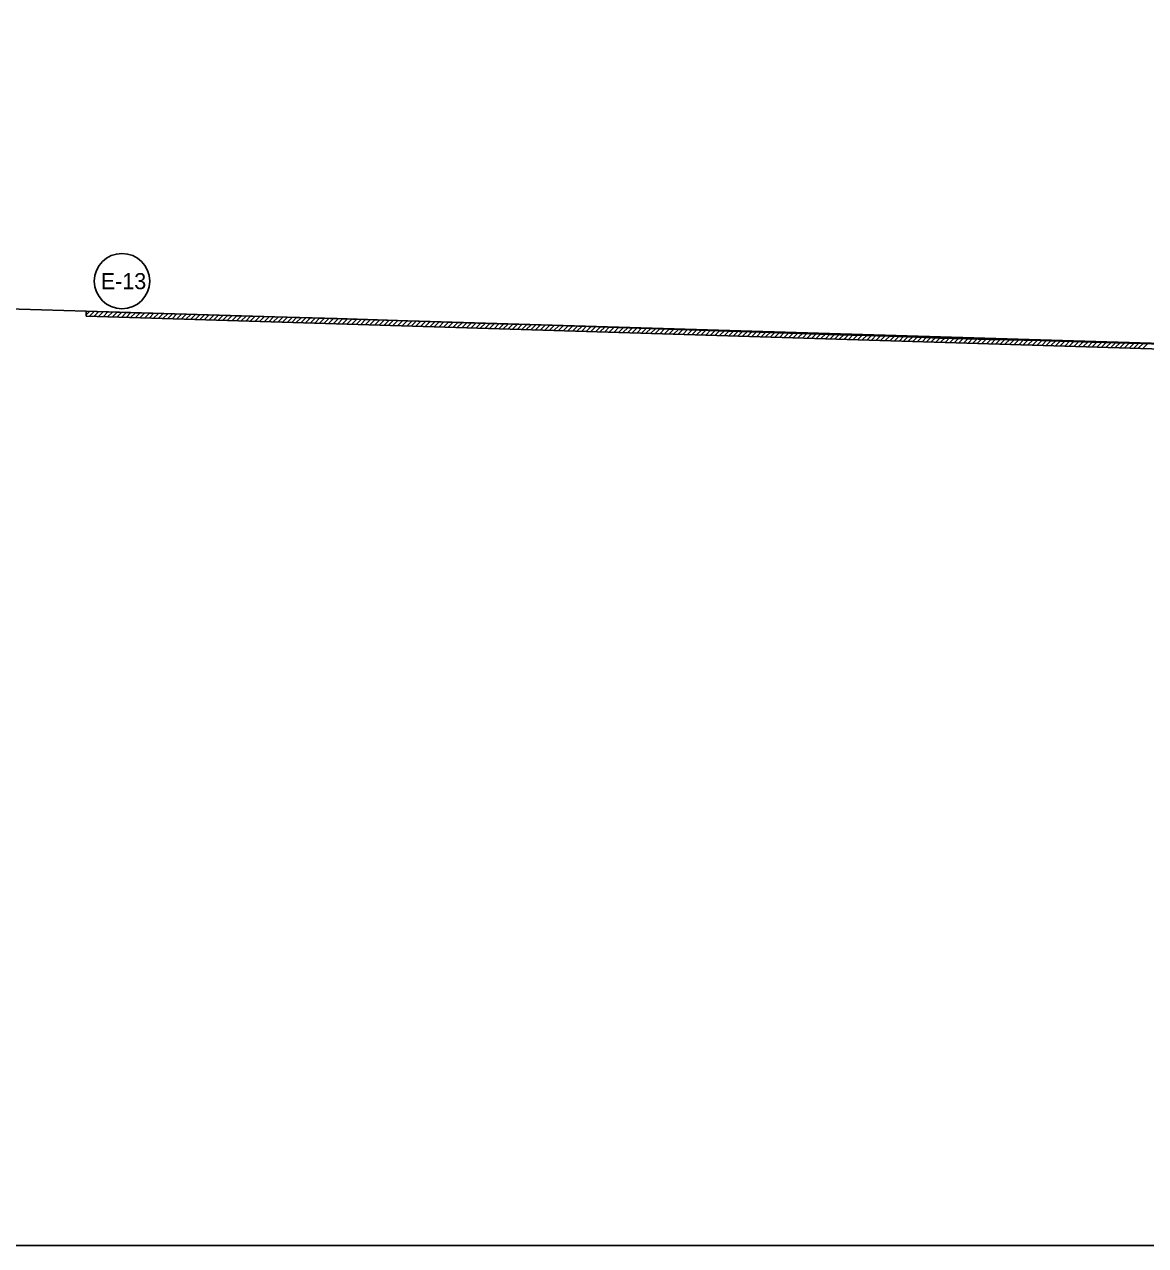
# Model space of a CAD drawing. Extents: x 976877 to 983987, y 1525984 to 1526526.
# Drawn here: x 982962.3 to 983296.7, y 1526043.8 to 1526408 of the extents above; entities that cross this region are included whole.
import ezdxf

# ---------------------------------------------------------------- set-up
doc = ezdxf.new("R2010")
doc.units = 0
doc.layers.add('R_Erosion', color=7, linetype='Continuous')
doc.layers.add('R_No Plot', color=7, linetype='Continuous')

msp = doc.modelspace()

# ---------------------------------------------------------------- linework, layer by layer
at = {"layer": 'R_Erosion'}
for p, q in [((982980.66, 1526320.94), (982980.7, 1526322.43)), ((982980.67, 1526321.39), (982981.69, 1526322.4)), ((982980.7, 1526322.43), (983619.57, 1526303.24)), ((982981.6, 1526320.91), (982983.06, 1526322.36)), ((982982.98, 1526320.86), (982984.43, 1526322.32)), ((982984.35, 1526320.82), (982985.81, 1526322.28)), ((982985.72, 1526320.78), (982987.18, 1526322.24)), ((982987.09, 1526320.74), (982988.55, 1526322.2)), ((982988.47, 1526320.7), (982989.93, 1526322.16)), ((982989.84, 1526320.66), (982991.3, 1526322.12)), ((982991.21, 1526320.61), (982992.67, 1526322.07)), ((982992.58, 1526320.57), (982994.04, 1526322.03)), ((982993.95, 1526320.53), (982995.42, 1526321.99)), ((982995.33, 1526320.49), (982996.79, 1526321.95)), ((982996.7, 1526320.45), (982998.16, 1526321.91)), ((982998.07, 1526320.4), (982999.54, 1526321.87)), ((983619.52, 1526301.48), (982980.66, 1526320.94)), ((982999.44, 1526320.36), (983000.91, 1526321.83)), ((983000.82, 1526320.32), (983002.28, 1526321.79)), ((983002.19, 1526320.28), (983003.65, 1526321.74)), ((983003.56, 1526320.24), (983005.03, 1526321.7)), ((983004.93, 1526320.2), (983006.4, 1526321.66)), ((983006.31, 1526320.15), (983007.77, 1526321.62)), ((983007.68, 1526320.11), (983009.15, 1526321.58)), ((983009.05, 1526320.07), (983010.52, 1526321.54)), ((983010.42, 1526320.03), (983011.89, 1526321.5)), ((983011.8, 1526319.99), (983013.27, 1526321.46)), ((983013.17, 1526319.94), (983014.64, 1526321.41)), ((983014.54, 1526319.9), (983016.01, 1526321.37)), ((983015.91, 1526319.86), (983017.38, 1526321.33)), ((983017.29, 1526319.82), (983018.76, 1526321.29)), ((983018.66, 1526319.78), (983020.13, 1526321.25)), ((983020.03, 1526319.74), (983021.5, 1526321.21)), ((983021.4, 1526319.69), (983022.88, 1526321.17)), ((983022.78, 1526319.65), (983024.25, 1526321.13)), ((983024.15, 1526319.61), (983025.62, 1526321.08)), ((983025.52, 1526319.57), (983027, 1526321.04)), ((983026.89, 1526319.53), (983028.37, 1526321)), ((983028.27, 1526319.49), (983029.74, 1526320.96)), ((983029.64, 1526319.44), (983031.11, 1526320.92)), ((983031.01, 1526319.4), (983032.49, 1526320.88)), ((983032.38, 1526319.36), (983033.86, 1526320.84)), ((983033.75, 1526319.32), (983035.23, 1526320.8)), ((983035.13, 1526319.28), (983036.61, 1526320.75)), ((983036.5, 1526319.23), (983037.98, 1526320.71)), ((983037.87, 1526319.19), (983039.35, 1526320.67)), ((983039.24, 1526319.15), (983040.72, 1526320.63)), ((983040.62, 1526319.11), (983042.1, 1526320.59)), ((983041.99, 1526319.07), (983043.47, 1526320.55)), ((983043.36, 1526319.03), (983044.84, 1526320.51)), ((983044.73, 1526318.98), (983046.22, 1526320.47)), ((983046.11, 1526318.94), (983047.59, 1526320.42)), ((983047.48, 1526318.9), (983048.96, 1526320.38)), ((983048.85, 1526318.86), (983050.34, 1526320.34)), ((983050.22, 1526318.82), (983051.71, 1526320.3)), ((983051.6, 1526318.77), (983053.08, 1526320.26)), ((983052.97, 1526318.73), (983054.45, 1526320.22)), ((983054.34, 1526318.69), (983055.83, 1526320.18)), ((983055.71, 1526318.65), (983057.2, 1526320.14)), ((983057.09, 1526318.61), (983058.57, 1526320.09)), ((983058.46, 1526318.57), (983059.95, 1526320.05)), ((983059.83, 1526318.52), (983061.32, 1526320.01)), ((983061.2, 1526318.48), (983062.69, 1526319.97)), ((983062.58, 1526318.44), (983064.06, 1526319.93)), ((983063.95, 1526318.4), (983065.44, 1526319.89)), ((983065.32, 1526318.36), (983066.81, 1526319.85)), ((983066.69, 1526318.31), (983068.18, 1526319.81)), ((983068.07, 1526318.27), (983069.56, 1526319.76)), ((983069.44, 1526318.23), (983070.93, 1526319.72)), ((983070.81, 1526318.19), (983072.3, 1526319.68)), ((983072.18, 1526318.15), (983073.68, 1526319.64)), ((983073.56, 1526318.11), (983075.05, 1526319.6)), ((983074.93, 1526318.06), (983076.42, 1526319.56)), ((983076.3, 1526318.02), (983077.79, 1526319.52)), ((983077.67, 1526317.98), (983079.17, 1526319.48)), ((983079.04, 1526317.94), (983080.54, 1526319.43)), ((983080.42, 1526317.9), (983081.91, 1526319.39)), ((983081.79, 1526317.85), (983083.29, 1526319.35)), ((983083.16, 1526317.81), (983084.66, 1526319.31)), ((983084.53, 1526317.77), (983086.03, 1526319.27)), ((983085.91, 1526317.73), (983087.41, 1526319.23)), ((983087.28, 1526317.69), (983088.78, 1526319.19)), ((983088.65, 1526317.65), (983090.15, 1526319.15)), ((983090.02, 1526317.6), (983091.52, 1526319.1)), ((983091.4, 1526317.56), (983092.9, 1526319.06)), ((983092.77, 1526317.52), (983094.27, 1526319.02)), ((983094.14, 1526317.48), (983095.64, 1526318.98)), ((983095.51, 1526317.44), (983097.02, 1526318.94)), ((983096.89, 1526317.4), (983098.39, 1526318.9)), ((983098.26, 1526317.35), (983099.76, 1526318.86)), ((983099.63, 1526317.31), (983101.13, 1526318.82)), ((983101, 1526317.27), (983102.51, 1526318.77)), ((983102.38, 1526317.23), (983103.88, 1526318.73)), ((983103.75, 1526317.19), (983105.25, 1526318.69)), ((983105.12, 1526317.14), (983106.63, 1526318.65)), ((983106.49, 1526317.1), (983108, 1526318.61)), ((983107.87, 1526317.06), (983109.37, 1526318.57)), ((983109.24, 1526317.02), (983110.75, 1526318.53)), ((983110.61, 1526316.98), (983112.12, 1526318.49)), ((983111.98, 1526316.94), (983113.49, 1526318.44)), ((983113.36, 1526316.89), (983114.86, 1526318.4)), ((983114.73, 1526316.85), (983116.24, 1526318.36)), ((983116.1, 1526316.81), (983117.61, 1526318.32)), ((983117.47, 1526316.77), (983118.98, 1526318.28)), ((983118.84, 1526316.73), (983120.36, 1526318.24)), ((983120.22, 1526316.68), (983121.73, 1526318.2)), ((983121.59, 1526316.64), (983123.1, 1526318.16)), ((983122.96, 1526316.6), (983124.48, 1526318.11)), ((983124.33, 1526316.56), (983125.85, 1526318.07)), ((983125.71, 1526316.52), (983127.22, 1526318.03)), ((983127.08, 1526316.48), (983128.59, 1526317.99)), ((983128.45, 1526316.43), (983129.97, 1526317.95)), ((983129.82, 1526316.39), (983131.34, 1526317.91)), ((983131.2, 1526316.35), (983132.71, 1526317.87)), ((983132.57, 1526316.31), (983134.09, 1526317.83)), ((983133.94, 1526316.27), (983135.46, 1526317.78)), ((983135.31, 1526316.23), (983136.83, 1526317.74)), ((983136.69, 1526316.18), (983138.2, 1526317.7)), ((983138.06, 1526316.14), (983139.58, 1526317.66)), ((983139.43, 1526316.1), (983140.95, 1526317.62)), ((983140.8, 1526316.06), (983142.32, 1526317.58)), ((983142.18, 1526316.02), (983143.7, 1526317.54)), ((983143.55, 1526315.97), (983145.07, 1526317.5)), ((983144.92, 1526315.93), (983146.44, 1526317.45)), ((983146.29, 1526315.89), (983147.82, 1526317.41)), ((983147.67, 1526315.85), (983149.19, 1526317.37)), ((983149.04, 1526315.81), (983150.56, 1526317.33)), ((983150.41, 1526315.77), (983151.93, 1526317.29)), ((983151.78, 1526315.72), (983153.31, 1526317.25)), ((983153.16, 1526315.68), (983154.68, 1526317.21)), ((983154.53, 1526315.64), (983156.05, 1526317.17)), ((983155.9, 1526315.6), (983157.43, 1526317.12)), ((983157.27, 1526315.56), (983158.8, 1526317.08)), ((983158.64, 1526315.51), (983160.17, 1526317.04)), ((983160.02, 1526315.47), (983161.55, 1526317)), ((983161.39, 1526315.43), (983162.92, 1526316.96)), ((983162.76, 1526315.39), (983164.29, 1526316.92)), ((983164.13, 1526315.35), (983165.66, 1526316.88)), ((983165.51, 1526315.31), (983167.04, 1526316.84)), ((983166.88, 1526315.26), (983168.41, 1526316.79)), ((983168.25, 1526315.22), (983169.78, 1526316.75)), ((983169.62, 1526315.18), (983171.16, 1526316.71)), ((983171, 1526315.14), (983172.53, 1526316.67)), ((983172.37, 1526315.1), (983173.9, 1526316.63)), ((983173.74, 1526315.05), (983175.27, 1526316.59)), ((983175.11, 1526315.01), (983176.65, 1526316.55)), ((983176.49, 1526314.97), (983178.02, 1526316.51)), ((983177.86, 1526314.93), (983179.39, 1526316.46)), ((983179.23, 1526314.89), (983180.77, 1526316.42)), ((983180.6, 1526314.85), (983182.14, 1526316.38)), ((983181.98, 1526314.8), (983183.51, 1526316.34)), ((983183.35, 1526314.76), (983184.89, 1526316.3)), ((983184.72, 1526314.72), (983186.26, 1526316.26)), ((983186.09, 1526314.68), (983187.63, 1526316.22)), ((983187.47, 1526314.64), (983189, 1526316.18)), ((983188.84, 1526314.59), (983190.38, 1526316.13)), ((983190.21, 1526314.55), (983191.75, 1526316.09)), ((983191.58, 1526314.51), (983193.12, 1526316.05)), ((983192.96, 1526314.47), (983194.5, 1526316.01)), ((983194.33, 1526314.43), (983195.87, 1526315.97)), ((983195.7, 1526314.39), (983197.24, 1526315.93)), ((983197.07, 1526314.34), (983198.61, 1526315.89)), ((983198.44, 1526314.3), (983199.99, 1526315.85)), ((983199.82, 1526314.26), (983201.36, 1526315.8)), ((983201.19, 1526314.22), (983202.73, 1526315.76)), ((983202.56, 1526314.18), (983204.11, 1526315.72)), ((983203.93, 1526314.14), (983205.48, 1526315.68)), ((983205.31, 1526314.09), (983206.85, 1526315.64)), ((983206.68, 1526314.05), (983208.23, 1526315.6)), ((983208.05, 1526314.01), (983209.6, 1526315.56)), ((983209.42, 1526313.97), (983210.97, 1526315.52)), ((983210.8, 1526313.93), (983212.34, 1526315.47)), ((983212.17, 1526313.88), (983213.72, 1526315.43)), ((983213.54, 1526313.84), (983215.09, 1526315.39)), ((983214.91, 1526313.8), (983216.46, 1526315.35)), ((983216.29, 1526313.76), (983217.84, 1526315.31)), ((983217.66, 1526313.72), (983219.21, 1526315.27)), ((983219.03, 1526313.68), (983220.58, 1526315.23)), ((983220.4, 1526313.63), (983221.96, 1526315.19)), ((983221.78, 1526313.59), (983223.33, 1526315.14)), ((983223.15, 1526313.55), (983224.7, 1526315.1)), ((983224.52, 1526313.51), (983226.07, 1526315.06)), ((983225.89, 1526313.47), (983227.45, 1526315.02)), ((983227.27, 1526313.42), (983228.82, 1526314.98)), ((983228.64, 1526313.38), (983230.19, 1526314.94)), ((983230.01, 1526313.34), (983231.57, 1526314.9)), ((983231.38, 1526313.3), (983232.94, 1526314.86)), ((983232.76, 1526313.26), (983234.31, 1526314.81)), ((983234.13, 1526313.22), (983235.68, 1526314.77)), ((983235.5, 1526313.17), (983237.06, 1526314.73)), ((983236.87, 1526313.13), (983238.43, 1526314.69)), ((983238.25, 1526313.09), (983239.8, 1526314.65)), ((983239.62, 1526313.05), (983241.18, 1526314.61)), ((983240.99, 1526313.01), (983242.55, 1526314.57)), ((983242.36, 1526312.96), (983243.92, 1526314.53)), ((983243.73, 1526312.92), (983245.3, 1526314.48)), ((983245.11, 1526312.88), (983246.67, 1526314.44)), ((983246.48, 1526312.84), (983248.04, 1526314.4)), ((983247.85, 1526312.8), (983249.41, 1526314.36)), ((983249.22, 1526312.76), (983250.79, 1526314.32)), ((983250.6, 1526312.71), (983252.16, 1526314.28)), ((983251.97, 1526312.67), (983253.53, 1526314.24)), ((983253.34, 1526312.63), (983254.91, 1526314.2)), ((983254.71, 1526312.59), (983256.28, 1526314.15)), ((983256.09, 1526312.55), (983257.65, 1526314.11)), ((983257.46, 1526312.51), (983259.03, 1526314.07)), ((983258.83, 1526312.46), (983260.4, 1526314.03)), ((983260.2, 1526312.42), (983261.77, 1526313.99)), ((983261.58, 1526312.38), (983263.14, 1526313.95)), ((983262.95, 1526312.34), (983264.52, 1526313.91)), ((983264.32, 1526312.3), (983265.89, 1526313.87)), ((983265.69, 1526312.25), (983267.26, 1526313.82)), ((983267.07, 1526312.21), (983268.64, 1526313.78)), ((983268.44, 1526312.17), (983270.01, 1526313.74)), ((983269.81, 1526312.13), (983271.38, 1526313.7)), ((983271.18, 1526312.09), (983272.75, 1526313.66)), ((983272.56, 1526312.05), (983274.13, 1526313.62)), ((983273.93, 1526312), (983275.5, 1526313.58)), ((983275.3, 1526311.96), (983276.87, 1526313.53)), ((983276.67, 1526311.92), (983278.25, 1526313.49)), ((983278.05, 1526311.88), (983279.62, 1526313.45)), ((983279.42, 1526311.84), (983280.99, 1526313.41)), ((983280.79, 1526311.79), (983282.37, 1526313.37)), ((983282.16, 1526311.75), (983283.74, 1526313.33)), ((983283.53, 1526311.71), (983285.11, 1526313.29)), ((983284.91, 1526311.67), (983286.48, 1526313.25)), ((983286.28, 1526311.63), (983287.86, 1526313.2)), ((983287.65, 1526311.59), (983289.23, 1526313.16)), ((983289.02, 1526311.54), (983290.6, 1526313.12)), ((983290.4, 1526311.5), (983291.98, 1526313.08)), ((983291.77, 1526311.46), (983293.35, 1526313.04)), ((983293.14, 1526311.42), (983294.72, 1526313)), ((983294.51, 1526311.38), (983296.09, 1526312.96)), ((983295.89, 1526311.33), (983297.47, 1526312.92))]:
    msp.add_line(p, q, dxfattribs=at)
msp.add_circle((982991.38, 1526331.41), 8.26, dxfattribs=at)
at = {"layer": 'R_No Plot'}
msp.add_line((982980.66, 1526322.43), (982819.58, 1526327.12), dxfattribs=at)
for points in [[(980311.86, 1526407.98), (980311.86, 1526043.76), (983987.45, 1526043.76), (983987.45, 1526292.17)], [(983310.46, 1526312.28), (983295.47, 1526312.78), (983280.48, 1526313.23), (983265.48, 1526313.66), (983250.49, 1526314.05), (983235.48, 1526314.43), (983220.49, 1526315.01), (983205.5, 1526315.43), (983205.49, 1526315.43), (983190.5, 1526315.91), (983175.51, 1526316.41), (983160.52, 1526316.88), (983145.51, 1526317.36), (983130.51, 1526317.85), (983115.52, 1526318.33), (983100.53, 1526318.76), (983085.54, 1526319.31), (983070.54, 1526319.74), (983055.55, 1526320.22), (983040.63, 1526320.68), (983025.63, 1526321.09), (983010.64, 1526321.57), (982995.65, 1526322), (982980.66, 1526322.43)]]:
    msp.add_lwpolyline(points, dxfattribs=at)

# ---------------------------------------------------------------- texts
at = {"layer": 'R_Erosion'}
msp.add_text('E-13', height=4.8, dxfattribs=at).set_placement((982985.05, 1526329.01))

doc.saveas('drawing.dxf')
